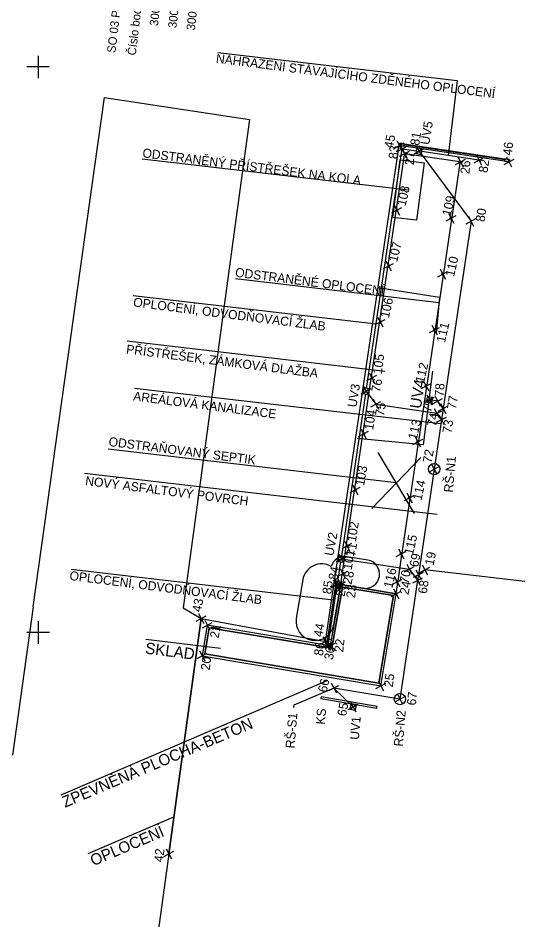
# Model space of a CAD drawing. Extents: x -734953 to -734775, y -1144697 to -1144368.
# Drawn here: x -734901.8 to -734857.6, y -1144575.4 to -1144495.7 of the extents above; entities that cross this region are included whole.
import ezdxf

# ---------------------------------------------------------------- set-up
doc = ezdxf.new("R2010")
doc.units = 0
for name, color, linetype in [('A3_BOURANÉ OBJEKTY', 7, 'Continuous'), ('A3_ODVODŇOVACÍ ŽLAB', 7, 'Continuous'), ('A3_SIT_OBJEKTY_N01', 7, 'Continuous'), ('A3_SIT_PNB', 7, 'Continuous'), ('CKSTENY_SRAF', 7, 'Continuous'), ('CKTEXTY_MALE', 7, 'Continuous'), ('Katastr_HRANICE DRÁHY', 7, 'Continuous'), ('PROGI_rozpiska', 7, 'Continuous'), ('PROGI_vytyč_body', 7, 'Continuous'), ('PROGI_vytyč_čísla', 7, 'Continuous'), ('SO01_CKKANALIZACE_JEDNOTNA_PODZ_N', 7, 'Continuous'), ('SO05_CKKANALIZACE_JEDNOTNA_PODZ_N', 7, 'Continuous'), ('čtvercová síť', 7, 'Continuous')]:
    doc.layers.add(name, color=color, linetype=linetype)

# ---------------------------------------------------------------- blocks, each defined once
blk = doc.blocks.new('POINT_DISPLAY')
for p, q in [((-0.35, -0.35), (0.35, 0.35)), ((-0.35, 0.35), (0.35, -0.35))]:
    blk.add_line(p, q)

msp = doc.modelspace()

# ---------------------------------------------------------------- linework, layer by layer
for p, q in [((-734884.128, -1144498.706), (-734862.977, -1144501.183)), ((-734866.625, -1144507.658), (-734866.057, -1144507.237)), ((-734891.587, -1144520.194), (-734870.126, -1144522.72)), ((-734892.113, -1144524.197), (-734869.354, -1144526.879)), ((-734891.483, -1144528.385), (-734864.408, -1144531.527)), ((-734871.293, -1144528.872), (-734870.725, -1144528.45)), ((-734865.695, -1144529.643), (-734865.127, -1144529.221)), ((-734895.885, -1144535.898), (-734864.742, -1144539.542)), ((-734873.494, -1144543.707), (-734872.926, -1144543.285)), ((-734897.087, -1144544.388), (-734873.9, -1144547.101)), ((-734890.472, -1144550.596), (-734883.888, -1144551.366)), ((-734897.944, -1144564.337), (-734874.447, -1144554.228)), ((-734872.456, -1144556.781), (-734871.88, -1144556.371)), ((-734895.581, -1144569.543), (-734887.99, -1144566.277))]:
    msp.add_line(p, q)
for points in [[(-734866.625, -1144507.658), (-734866.13, -1144507.731), (-734866.057, -1144507.237), (-734866.551, -1144507.163)], [(-734866.625, -1144507.658), (-734866.13, -1144507.731), (-734866.057, -1144507.237)], [(-734871.293, -1144528.872), (-734870.798, -1144528.945), (-734870.725, -1144528.45), (-734871.219, -1144528.377)], [(-734871.293, -1144528.872), (-734870.798, -1144528.945), (-734870.725, -1144528.45)], [(-734865.695, -1144529.643), (-734865.201, -1144529.716), (-734865.127, -1144529.221), (-734865.622, -1144529.148)], [(-734865.695, -1144529.643), (-734865.201, -1144529.716), (-734865.127, -1144529.221)], [(-734873.494, -1144543.707), (-734873, -1144543.78), (-734872.926, -1144543.285), (-734873.421, -1144543.212)], [(-734873.494, -1144543.707), (-734873, -1144543.78), (-734872.926, -1144543.285)], [(-734872.456, -1144556.781), (-734871.963, -1144556.864), (-734871.88, -1144556.371), (-734872.373, -1144556.288)], [(-734872.456, -1144556.781), (-734871.963, -1144556.864), (-734871.88, -1144556.371)]]:
    msp.add_lwpolyline(points, close=True)
at = {"layer": 'A3_BOURANÉ OBJEKTY'}
for p, q in [((-734866.751, -1144539.477), (-734869.95, -1144534.072)), ((-734866.175, -1144534.51), (-734870.526, -1144539.039))]:
    msp.add_line(p, q, dxfattribs=at)
msp.add_lwpolyline([(-734866.552, -1144513.548), (-734868.669, -1144513.299), (-734867.996, -1144508.198), (-734865.894, -1144508.483)], close=True, dxfattribs=at)
for points in [[(-734869.977, -1144519.507), (-734864.523, -1144520.336), (-734864.819, -1144523.525)], [(-734865.166, -1144526.906), (-734865.978, -1144533.409), (-734871.807, -1144532.846)]]:
    msp.add_lwpolyline(points, dxfattribs=at)
at = {"layer": 'A3_ODVODŇOVACÍ ŽLAB'}
for points in [[(-734870.972, -1144528.414), (-734867.824, -1144507.227), (-734866.588, -1144507.411)], [(-734861.049, -1144508.234), (-734866.093, -1144507.484)], [(-734873.174, -1144543.249), (-734871.046, -1144528.908)], [(-734874.496, -1144551.113), (-734873.702, -1144545.773), (-734873.54, -1144545.701), (-734873.249, -1144543.743)]]:
    msp.add_lwpolyline(points, dxfattribs=at)
at = {"layer": 'A3_SIT_OBJEKTY_N01'}
for p, q in [((-734867.491, -1144507.64), (-734867.62, -1144507.621)), ((-734867.487, -1144507.681), (-734867.483, -1144507.651)), ((-734862.694, -1144508.352), (-734862.823, -1144508.333)), ((-734873.262, -1144545.743), (-734874.2, -1144551.163)), ((-734874.036, -1144551.393), (-734873.099, -1144545.974)), ((-734868.356, -1144546.569), (-734873.262, -1144545.743)), ((-734873.099, -1144545.974), (-734868.587, -1144546.733)), ((-734868.587, -1144546.733), (-734869.889, -1144554.474)), ((-734869.725, -1144554.704), (-734868.356, -1144546.569)), ((-734885.047, -1144549.338), (-734885.503, -1144552.05)), ((-734885.273, -1144551.886), (-734884.883, -1144549.568)), ((-734874.2, -1144551.163), (-734885.047, -1144549.338)), ((-734884.883, -1144549.568), (-734874.036, -1144551.393)), ((-734869.889, -1144554.474), (-734885.273, -1144551.886)), ((-734885.503, -1144552.05), (-734869.725, -1144554.704)), ((-734875, -1144555.695), (-734875.026, -1144555.843)), ((-734875.026, -1144555.843), (-734870.057, -1144556.677)), ((-734870.032, -1144556.529), (-734875, -1144555.695)), ((-734870.057, -1144556.677), (-734870.032, -1144556.529))]:
    msp.add_line(p, q, dxfattribs=at)
for points in [[(-734888.44, -1144569.554), (-734887.65, -1144563.8), (-734885.58, -1144548.75), (-734874.6, -1144550.79), (-734868.084, -1144506.936)], [(-734868.084, -1144506.936), (-734868.055, -1144506.738), (-734867.659, -1144506.797), (-734867.689, -1144506.994), (-734868.084, -1144506.936)], [(-734858.772, -1144508.218), (-734867.674, -1144506.895)], [(-734867.631, -1144507.629), (-734867.652, -1144507.767), (-734867.504, -1144507.79), (-734867.487, -1144507.681)], [(-734862.834, -1144508.342), (-734862.838, -1144508.372), (-734862.855, -1144508.48), (-734862.706, -1144508.502), (-734862.686, -1144508.364)], [(-734858.391, -1144508.376), (-734858.786, -1144508.317), (-734858.757, -1144508.119), (-734858.361, -1144508.178), (-734858.391, -1144508.376)], [(-734868.216, -1144512.587), (-734868.365, -1144512.565), (-734868.387, -1144512.713), (-734868.238, -1144512.735), (-734868.216, -1144512.587)], [(-734863.419, -1144513.3), (-734863.567, -1144513.278), (-734863.589, -1144513.426), (-734863.441, -1144513.448), (-734863.419, -1144513.3)], [(-734868.951, -1144517.533), (-734869.099, -1144517.511), (-734869.122, -1144517.659), (-734868.973, -1144517.681), (-734868.951, -1144517.533)], [(-734864.154, -1144518.245), (-734864.302, -1144518.223), (-734864.324, -1144518.372), (-734864.176, -1144518.394), (-734864.154, -1144518.245)], [(-734869.686, -1144522.478), (-734869.834, -1144522.456), (-734869.856, -1144522.605), (-734869.708, -1144522.627), (-734869.686, -1144522.478)], [(-734864.889, -1144523.191), (-734865.037, -1144523.169), (-734865.059, -1144523.317), (-734864.911, -1144523.339), (-734864.889, -1144523.191)], [(-734870.421, -1144527.424), (-734870.569, -1144527.402), (-734870.591, -1144527.55), (-734870.443, -1144527.572), (-734870.421, -1144527.424)], [(-734865.623, -1144528.137), (-734865.772, -1144528.115), (-734865.794, -1144528.263), (-734865.645, -1144528.285), (-734865.623, -1144528.137)], [(-734871.156, -1144532.37), (-734871.304, -1144532.348), (-734871.326, -1144532.496), (-734871.178, -1144532.518), (-734871.156, -1144532.37)], [(-734866.358, -1144533.082), (-734866.507, -1144533.06), (-734866.529, -1144533.209), (-734866.38, -1144533.231), (-734866.358, -1144533.082)], [(-734871.89, -1144537.315), (-734872.039, -1144537.293), (-734872.061, -1144537.442), (-734871.912, -1144537.464), (-734871.89, -1144537.315)], [(-734867.093, -1144538.028), (-734867.241, -1144538.006), (-734867.263, -1144538.155), (-734867.115, -1144538.177), (-734867.093, -1144538.028)], [(-734872.625, -1144542.261), (-734872.774, -1144542.239), (-734872.796, -1144542.387), (-734872.647, -1144542.41), (-734872.625, -1144542.261)], [(-734867.828, -1144542.974), (-734867.976, -1144542.952), (-734867.998, -1144543.1), (-734867.85, -1144543.122), (-734867.828, -1144542.974)], [(-734873.163, -1144544.86), (-734873.015, -1144544.882), (-734872.993, -1144544.734), (-734873.141, -1144544.712), (-734873.163, -1144544.86)], [(-734868.195, -1144545.447), (-734868.344, -1144545.425), (-734868.366, -1144545.573), (-734868.217, -1144545.595), (-734868.195, -1144545.447)], [(-734873.262, -1144545.743), (-734873.293, -1144545.738), (-734873.603, -1144545.787), (-734874.397, -1144551.13)]]:
    msp.add_lwpolyline(points, dxfattribs=at)
for points in [[(-734868.055, -1144506.738), (-734868.084, -1144506.936), (-734867.689, -1144506.994), (-734867.659, -1144506.797)], [(-734867.659, -1144506.797), (-734858.757, -1144508.119), (-734858.786, -1144508.317), (-734867.689, -1144506.994)], [(-734869.708, -1144522.627), (-734869.856, -1144522.605), (-734870.569, -1144527.402), (-734870.421, -1144527.424), (-734870.443, -1144527.572), (-734870.591, -1144527.55), (-734871.304, -1144532.348), (-734871.156, -1144532.37), (-734871.178, -1144532.518), (-734871.326, -1144532.496), (-734872.039, -1144537.293), (-734871.89, -1144537.315), (-734871.912, -1144537.464), (-734872.061, -1144537.442), (-734872.774, -1144542.239), (-734872.625, -1144542.261), (-734872.647, -1144542.41), (-734872.796, -1144542.387), (-734873.141, -1144544.712), (-734872.993, -1144544.734), (-734873.015, -1144544.882), (-734873.163, -1144544.86), (-734873.293, -1144545.738), (-734868.362, -1144546.568), (-734868.217, -1144545.595), (-734868.366, -1144545.573), (-734868.344, -1144545.425), (-734868.195, -1144545.447), (-734867.85, -1144543.122), (-734867.998, -1144543.1), (-734867.976, -1144542.952), (-734867.828, -1144542.974), (-734867.115, -1144538.177), (-734867.263, -1144538.155), (-734867.241, -1144538.006), (-734867.093, -1144538.028), (-734866.38, -1144533.231), (-734866.529, -1144533.209), (-734866.507, -1144533.06), (-734866.358, -1144533.082), (-734865.645, -1144528.285), (-734865.794, -1144528.263), (-734865.772, -1144528.115), (-734865.623, -1144528.137), (-734864.911, -1144523.339), (-734865.059, -1144523.317), (-734865.037, -1144523.169), (-734864.889, -1144523.191), (-734864.176, -1144518.394), (-734864.324, -1144518.372), (-734864.302, -1144518.223), (-734864.154, -1144518.245), (-734863.441, -1144513.448), (-734863.589, -1144513.426), (-734863.567, -1144513.278), (-734863.419, -1144513.3), (-734862.706, -1144508.502), (-734862.855, -1144508.48), (-734862.838, -1144508.372), (-734862.937, -1144508.357), (-734867.389, -1144507.696), (-734867.487, -1144507.681), (-734867.504, -1144507.79), (-734867.652, -1144507.767), (-734868.365, -1144512.565), (-734868.216, -1144512.587), (-734868.238, -1144512.735), (-734868.387, -1144512.713), (-734869.099, -1144517.511), (-734868.951, -1144517.533), (-734868.973, -1144517.681), (-734869.122, -1144517.659), (-734869.834, -1144522.456), (-734869.686, -1144522.478)], [(-734858.786, -1144508.317), (-734858.391, -1144508.376), (-734858.361, -1144508.178), (-734858.757, -1144508.119)], [(-734869.725, -1144554.704), (-734868.356, -1144546.569), (-734873.262, -1144545.743), (-734874.2, -1144551.163), (-734885.047, -1144549.338), (-734885.503, -1144552.05)], [(-734869.889, -1144554.474), (-734868.587, -1144546.733), (-734873.099, -1144545.974), (-734874.036, -1144551.393), (-734884.883, -1144549.568), (-734885.273, -1144551.886)], [(-734875.026, -1144555.843), (-734870.057, -1144556.677), (-734870.032, -1144556.529), (-734875, -1144555.695)]]:
    msp.add_lwpolyline(points, close=True, dxfattribs=at)
for centre, start, end in [((-734867.621, -1144507.63), 81.54908, 171.54908), ((-734867.493, -1144507.65), 351.54908, 81.54908), ((-734862.824, -1144508.343), 81.54908, 171.54908), ((-734862.695, -1144508.362), 351.54908, 81.54908)]:
    msp.add_arc(centre, 0.01, start, end, dxfattribs=at)
at = {"layer": 'A3_SIT_PNB'}
for points in [[(-734870.874, -1144543.6), (-734872.698, -1144543.293)], [(-734876.611, -1144545.332), (-734877.183, -1144548.734)], [(-734873.86, -1144549.293), (-734873.287, -1144545.891), (-734873.262, -1144545.743), (-734873.114, -1144545.768), (-734871.29, -1144546.075)]]:
    msp.add_lwpolyline(points, dxfattribs=at)
for centre, radius, start, end in [((-734874.949, -1144545.612), 1.685, 59.88428, 170.44851), ((-734872.906, -1144544.531), 1.255, 80.4474, 162.539), ((-734871.082, -1144544.838), 1.255, 260.44926, 80.44926), ((-734875.521, -1144549.014), 1.685, 170.44926, 350.44926)]:
    msp.add_arc(centre, radius, start, end, dxfattribs=at)
at = {"layer": 'CKSTENY_SRAF'}
msp.add_line((-734885.58, -1144548.75), (-734886.194, -1144553.213), dxfattribs=at)
at = {"layer": 'CKTEXTY_MALE'}
for p, q in [((-734862.977, -1144501.183), (-734863.755, -1144507.829)), ((-734867.282, -1144510.891), (-734890.793, -1144508.14)), ((-734864.572, -1144520.862), (-734882.554, -1144518.732)), ((-734868.35, -1144536.774), (-734893.795, -1144533.797)), ((-734877.406, -1144556.428), (-734877.429, -1144556.626))]:
    msp.add_line(p, q, dxfattribs=at)
msp.add_lwpolyline([(-734873.87, -1144554.906), (-734877.406, -1144556.428)], dxfattribs=at)
at = {"layer": 'Katastr_HRANICE DRÁHY'}
for p, q in [((-734900.43, -1144547.74), (-734901.55, -1144555.77)), ((-734901.55, -1144555.77), (-734902.26, -1144560.85))]:
    msp.add_line(p, q, dxfattribs=at)
for points in [[(-734895.01, -1144508.96), (-734894.14, -1144502.71)], [(-734894.14, -1144502.71), (-734881.31, -1144504.63)], [(-734881.31, -1144504.63), (-734882.78, -1144515.44)], [(-734897.31, -1144525.39), (-734895.01, -1144508.96)], [(-734882.78, -1144515.44), (-734885, -1144531.74)], [(-734898.48, -1144533.77), (-734897.31, -1144525.39)], [(-734885, -1144531.74), (-734886.21, -1144540.66)], [(-734899.43, -1144540.59), (-734898.48, -1144533.77)], [(-734900.43, -1144547.74), (-734899.43, -1144540.59)], [(-734886.21, -1144540.66), (-734887.18, -1144547.81)], [(-734887.18, -1144547.81), (-734885.58, -1144548.75)], [(-734885.58, -1144548.75), (-734887.65, -1144563.8)], [(-734887.65, -1144563.8), (-734889.5, -1144577.27)]]:
    msp.add_lwpolyline(points, dxfattribs=at)
at = {"layer": 'SO01_CKKANALIZACE_JEDNOTNA_PODZ_N'}
msp.add_lwpolyline([(-734852.237, -1144546.036), (-734854.223, -1144545.804), (-734854.72, -1144545.746), (-734865.823, -1144544.448), (-734866.393, -1144544.885)], dxfattribs=at)
at = {"layer": 'SO05_CKKANALIZACE_JEDNOTNA_PODZ_N'}
msp.add_line((-734872.168, -1144556.576), (-734873.869, -1144554.902), dxfattribs=at)
for points in [[(-734866.341, -1144507.447), (-734861.751, -1144513.639), (-734864.21, -1144530.193), (-734864.357, -1144531.183), (-734866.393, -1144544.885), (-734866.467, -1144545.379), (-734868.027, -1144555.885), (-734873.869, -1144554.902)], [(-734871.009, -1144528.661), (-734870.152, -1144529.816), (-734864.775, -1144530.615), (-734864.357, -1144531.183)], [(-734864.21, -1144530.193), (-734864.695, -1144529.538), (-734865.411, -1144529.432)], [(-734873.21, -1144543.496), (-734867.201, -1144544.389), (-734866.467, -1144545.379)]]:
    msp.add_lwpolyline(points, dxfattribs=at)
for centre in [(-734865.006, -1144535.549), (-734868.027, -1144555.884)]:
    msp.add_circle(centre, 0.5, dxfattribs=at)
at = {"layer": 'čtvercová síť'}
for p, q in [((-734900, -1144499), (-734900, -1144501)), ((-734899, -1144500), (-734901, -1144500)), ((-734900, -1144549), (-734900, -1144551)), ((-734899, -1144550), (-734901, -1144550))]:
    msp.add_line(p, q, dxfattribs=at)

# ---------------------------------------------------------------- block references
at = {"layer": 'PROGI_vytyč_body', "rotation": -17.15277001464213}
for p in [(-734868.084, -1144506.936), (-734867.824, -1144507.227), (-734867.636, -1144507.659), (-734866.341, -1144507.447), (-734862.69, -1144508.394), (-734861.049, -1144508.234), (-734858.391, -1144508.376), (-734868.301, -1144512.65), (-734863.504, -1144513.363), (-734861.751, -1144513.639), (-734869.036, -1144517.596), (-734864.239, -1144518.309), (-734869.771, -1144522.541), (-734864.974, -1144523.254), (-734870.506, -1144527.487), (-734865.709, -1144528.2), (-734871.009, -1144528.661), (-734870.152, -1144529.816), (-734865.411, -1144529.432), (-734864.695, -1144529.538), (-734864.775, -1144530.615), (-734864.21, -1144530.193), (-734864.357, -1144531.183), (-734871.241, -1144532.433), (-734866.443, -1144533.146), (-734865.006, -1144535.549), (-734871.976, -1144537.379), (-734867.178, -1144538.091), (-734872.71, -1144542.324), (-734873.21, -1144543.496), (-734867.913, -1144543.037), (-734867.201, -1144544.389), (-734873.078, -1144544.797), (-734866.393, -1144544.885), (-734873.702, -1144545.773), (-734873.603, -1144545.787), (-734873.54, -1144545.701), (-734873.293, -1144545.738), (-734873.262, -1144545.743), (-734868.28, -1144545.51), (-734866.467, -1144545.379), (-734868.362, -1144546.568), (-734885.58, -1144548.75), (-734885.047, -1144549.338), (-734874.6, -1144550.79), (-734874.496, -1144551.113), (-734874.397, -1144551.13), (-734874.2, -1144551.163), (-734885.503, -1144552.05), (-734869.725, -1144554.704), (-734873.87, -1144554.906), (-734868.027, -1144555.885), (-734872.168, -1144556.576), (-734888.44, -1144569.554)]:
    msp.add_blockref('POINT_DISPLAY', p, dxfattribs=at)
at = {"layer": 'PROGI_vytyč_čísla', "rotation": -17.15277001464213}
msp.add_blockref('POINT_DISPLAY', (-734865.823, -1144544.448), dxfattribs=at)

# ---------------------------------------------------------------- texts
at = {"layer": 'PROGI_rozpiska'}
for s, height, rotation, p in [('          30026     734862.690    1144508.394                              RD_SKLAD', 0.75, 83.18695, (-734889.741, -1144499.169)), ('          30027     734867.636    1144507.659                              RD_SKLAD', 0.75, 83.18695, (-734888.114, -1144499.363)), ('          30028     734873.293    1144545.738                              RD_SKLAD', 0.75, 83.18695, (-734886.488, -1144499.558)), ('Číslo bodu                     Y                         X                    Z             Popis', 0.75, 83.18695, (-734891.371, -1144499.009)), ('SO 03 Přístřešek parkovacích stání', 0.75, 83.18695, (-734893.169, -1144498.791)), ('NAHRAZENÍ STÁVAJÍCÍHO ZDĚNÉHO OPLOCENÍ', 0.8, 352.74798, (-734884.316, -1144499.617)), ('UV5', 0.8, 80.62415, (-734865.447, -1144506.921)), ('ODSTRANĚNÝ PŘÍSTŘEŠEK NA KOLA', 0.8, 352.74798, (-734890.809, -1144507.976)), ('ODSTRANĚNÉ OPLOCENÍ', 0.8, 352.74798, (-734882.625, -1144518.531)), ('OPLOCENÍ, ODVODŇOVACÍ ŽLAB', 0.8, 352.74798, (-734891.627, -1144521.167)), ('PŘÍSTŘEŠEK, ZÁMKOVÁ DLAŽBA', 0.8, 352.74798, (-734892.248, -1144525.326)), ('UV3', 0.8, 80.62415, (-734871.883, -1144530.136)), ('UV4', 1, 80.95199, (-734866.185, -1144530.263)), ('AREÁLOVÁ KANALIZACE', 0.8, 352.74798, (-734891.626, -1144529.475)), ('ODSTRAŇOVANÝ SEPTIK', 0.8, 352.74798, (-734893.799, -1144533.497)), ('RŠ-N1', 0.8, 85.20554, (-734863.351, -1144537.641)), ('NOVÝ ASFALTOVÝ POVRCH', 0.8, 352.74798, (-734895.862, -1144536.954)), ('UV2', 0.8, 79.50111, (-734873.918, -1144543.266)), ('OPLOCENÍ, ODVODŇOVACÍ ŽLAB', 0.8, 352.74798, (-734897.255, -1144545.346)), ('SKLAD', 1, 352.74798, (-734890.575, -1144551.85)), ('ZPEVNĚNÁ PLOCHA-BETON', 1, 22.98029, (-734897.613, -1144565.495)), ('RŠ-S1', 0.8, 85.20554, (-734877.347, -1144560.263)), ('KS', 0.8, 85.20554, (-734874.669, -1144558.157)), ('UV1', 0.8, 85.20554, (-734871.661, -1144559.507)), ('RŠ-N2', 0.8, 85.20554, (-734867.778, -1144560.1)), ('OPLOCENÍ', 1, 22.98029, (-734895.125, -1144570.663))]:
    msp.add_text(s, height=height, rotation=rotation, dxfattribs=at).set_placement(p)
at = {"layer": 'PROGI_vytyč_čísla'}
for s, rotation, p in [('45', 79.36703, (-734868.648, -1144507.235)), ('81', 80.66153, (-734866.347, -1144506.987)), ('83', 84.61851, (-734868.247, -1144508.164)), ('46', 83.61032, (-734858.153, -1144507.855)), ('27', 89.74533, (-734866.791, -1144508.675)), ('26', 84.41008, (-734861.903, -1144509.486)), ('82', 81.23196, (-734860.306, -1144509.397)), ('108', 77.04603, (-734867.543, -1144512.351)), ('109', 77.04603, (-734863.546, -1144513.23)), ('80', 81.83176, (-734860.564, -1144513.731)), ('107', 77.04603, (-734868.278, -1144517.296)), ('110', 77.04603, (-734863.253, -1144518.589)), ('106', 77.04603, (-734869.013, -1144522.242)), ('111', 77.04603, (-734864.057, -1144524.421)), ('105', 82.63448, (-734869.638, -1144527.198)), ('112', 77.04603, (-734865.91, -1144527.981)), ('76', 79.48443, (-734869.794, -1144528.806)), ('78', 86.33314, (-734864.161, -1144529.168)), ('79', 83.19755, (-734865.244, -1144530.58)), ('77', 81.62315, (-734863.083, -1144530.299)), ('104', 81.44238, (-734870.406, -1144532.134)), ('75', 81.42217, (-734869.443, -1144530.905)), ('113', 77.04603, (-734866.549, -1144532.996)), ('74', 78.3972, (-734864.856, -1144531.829)), ('73', 80.75717, (-734863.504, -1144532.426)), ('72', 79.50978, (-734865.243, -1144535.058)), ('103', 80.27519, (-734871.204, -1144537.075)), ('114', 77.04603, (-734866.143, -1144538.366)), ('102', 81.44236, (-734871.923, -1144542.022)), ('115', 77.04603, (-734866.885, -1144543.186)), ('71', 82.0651, (-734871.975, -1144543.308)), ('101', 81.44236, (-734872.29, -1144544.495)), ('69', 79.82055, (-734866.413, -1144544.251)), ('19', 78.87342, (-734865.064, -1144544.121)), ('84', 78.94435, (-734873.583, -1144545.415)), ('28', 77.04603, (-734872.331, -1144545.801)), ('116', 77.04603, (-734868.709, -1144546.126)), ('70', 78.01402, (-734867.315, -1144545.725)), ('85', 82.42056, (-734874.101, -1144546.643)), ('24', 79.00725, (-734867.283, -1144546.695)), ('68', 81.8369, (-734865.655, -1144546.604)), ('29', 80.46834, (-734872.922, -1144546.862)), ('23', 82.59214, (-734872.001, -1144546.986)), ('43', 79.24433, (-734885.61, -1144548.241)), ('21', 79.43804, (-734884.057, -1144550.545)), ('44', 79.58648, (-734874.886, -1144550.441)), ('86', 82.18201, (-734874.839, -1144552.092)), ('22', 83.8257, (-734873.046, -1144551.781)), ('30', 80.77209, (-734873.95, -1144552.461)), ('20', 83.19909, (-734884.836, -1144553.365)), ('66', 77.28779, (-734874.51, -1144555.345)), ('25', 82.18264, (-734868.669, -1144554.863)), ('67', 83.79985, (-734866.633, -1144556.471)), ('65', 79.53692, (-734872.79, -1144557.439)), ('42', 83.57862, (-734888.961, -1144570.33))]:
    msp.add_text(s, height=0.8, rotation=rotation, dxfattribs=at).set_placement(p)

doc.saveas('drawing.dxf')
